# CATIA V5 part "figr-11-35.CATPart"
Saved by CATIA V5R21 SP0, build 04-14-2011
Part number: Part1
Bounding box of the stored display mesh (mm): x -55 to 66, y 20 to 170, z -50 to 0
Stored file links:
  D:\CATIA V5R21 E-RESOURCES\CATIA-V5R21\catia-v5r21-prt\c11-catia-v5r21-prt\c11-catia-v5r21-figr-11-35.CATPart
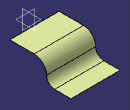
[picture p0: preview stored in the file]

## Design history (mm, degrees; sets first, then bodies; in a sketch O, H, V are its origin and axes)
Set1
  Extrude1: Element1 Sketch1, Lim1 66, Lim2 55, Direction yz-plane
  Symmetry1: ToTransfor Extrude1, Reference zx-plane
Body1 (main body)
  Sketch1 on yz-plane, origin (0, 0, 0), H (0, 1, 0), V (0, 0, 1)
    point P1 (20, 0)
    line L1 (20, 0) -> (80, 0)
    arc A1 centre (80, -30) radius 30 from (80, 0) to (110, -30) cw
    arc A2 centre (130, -30) radius 20 from (110, -30) to (130, -50) ccw
    line L2 (130, -50) -> (170, -50)
    coincidence: P1 H
    horizontal: L1 H
    tangency: A1 L1, A2 A1, L2 A2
